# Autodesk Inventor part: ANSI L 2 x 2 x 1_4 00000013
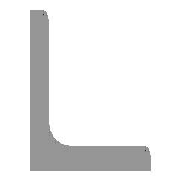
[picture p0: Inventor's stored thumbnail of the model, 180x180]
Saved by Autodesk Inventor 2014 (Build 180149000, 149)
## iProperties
_FrameMemberDoc: Frame Member File
_Version: 15.0.0
_CCFamilyMember: 11
_CCFamilyDisplayName: ANSI L (Equal angles) - Angle Steel
Created: 2007-02
Part Number: ANSI L 2 x 2 x 1_4 00000013
Material: Steel, Mild
Document SubType Name: Modeling
Standard: AISC
Designer: Autodesk, Inc.
Size Designation: L 2 x 2 x 1/4
Stock Number: L 2 x 2 x 1/4
Density: 7.86 g/cm^3
Description: Angle Steel
Standards Organization: ANSI
Language: en-US
Categories: <MemberInstance><Categories><Category DisplayName="Structural Shapes" InternalName="089c4875-fa83-4c05-b084-43b9cc11f5ed" Mnemonic="GRDR"><CategoryParameter Dis
Mass: 2878.9 g
Surface Area: 1206.61 cm^2
Volume: 366.272 cm^3
Appearance: Steel
IsCustomPart: 1
G_L: 24.393 in
G_W: 2.000 in
G_H: 2.000 in
+1B0D5935-5D52-4120-8208-152CEE6E40CF+CUTDETAIL1: Miter 45.00 deg
+F2A5F158-765A-4D33-8A85-CF833D4C658B+CUTDETAIL2: Cut
Author: Autodesk, Inc.
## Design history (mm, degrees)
node "Start plane"
node "End plane"
sketch "Sketch"
  geometry: L1 (50.8, 0)-(0, 0); L2 (0, 0)-(0, 50.8); L3 (0, 50.8)-(3.302, 50.8); L4 (6.35, 47.752)-(6.35, 12.7); L5 (12.7, 6.35)-(47.752, 6.35); L6 (50.8, 3.302)-(50.8, 0); L7 (0, -11.041)-(0, 31.538); L8 (-11.041, 0)-(31.538, 0); L9 (0, 63.926)-(0, -23.536) reference; L10 (-23.536, 0)-(63.926, 0) reference; A1 r 6.35 centre (12.7, 12.7) between (6.35, 12.7) and (12.7, 6.35); A2 r 3.048 centre (3.302, 47.752) between (6.35, 47.752) and (3.302, 50.8); A3 r 3.048 centre (47.752, 3.302) between (50.8, 3.302) and (47.752, 6.35); 3 further points
  constraints: 16 end point, 6 point on circle, 6 point on line, 6 tangent, 4 parallel, 3 centre point, 2 collinear, 1 equal radius, 1 horizontal, 1 perpendicular
  dimensions: "d0" = 50.8 distance between parallel lines of L6 L2 (= G_H); "d1" = 50.8 distance between parallel lines of L3 L1 (= G_H); "d2" = 6.35 distance between parallel lines of L2 L4 (= G_T); "d3" = 6.35 distance between parallel lines of L1 L5 (= G_T); "d10" = 0 distance between parallel lines of L7 L2 (computed from ex); "d11" = 0 distance between parallel lines of L8 L1 (computed from d10); "d14" = 6.35 radius of A1 (= G_IR); "d15" = 3.048 radius of A2 (= G_ER)
extrude "Body" new body sketch "Sketch" stored distance "d4" = 619.5695 (= G_L); taper "d5" = 0 deg
node "Driven Length"
  sketch "Sketch4"
    geometry: L1 (0, 0)-(10, 0) reference
    constraints: 2 end point, 1 horizontal
  workplane "Work Plane5"
  sketch "Sketch5"
    geometry: L1 (-2, 6.35)-(12, 6.35) reference; L2 (-2, 625.919)-(12, 625.919) reference
    dimensions: "d19" = 619.5695 distance between parallel lines of L1 L2 (derived)
workplane "Work Plane3"
split "Split1"
workplane "Work Plane4"
split "Split2"
sketch "Sketch3"
  geometry: C1 r 8.331 at (34.925, 263.97) reference; C2 r 8.331 at (34.925, 581.47) reference
  constraints: 2 centre point, 4 other
extrude "Extrusion2" cut sketch "Sketch3" stored distance "d16" = 25.4; taper "d17" = 0 deg
body "Solid1"
other parameters: "G_H" = 50.8 [user parameter; used in 2 equation terms], "G_T" = 6.35 [user parameter; used in 2 equation terms], "G_ER" = 3.048 [user parameter; used in 1 equation term], "G_IR" = 6.35 [user parameter; used in 1 equation term], "G_L" = 619.5695 (= d19) [user parameter; used in 1 equation term], "ex" = 0 [user parameter; used in 1 equation term], "G_OFFSET_START" = -6.35 [user parameter; used in 1 equation term], "G_OFFSET_END" = 0 [user parameter; used in 1 equation term], "d12" = 6.35 (= -G_OFFSET_START), "d13" = 625.9195 (= G_OFFSET_END + B_L), "B_L" = 625.9195 [user parameter; used in 1 equation term], "d18" = 90 deg
